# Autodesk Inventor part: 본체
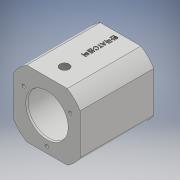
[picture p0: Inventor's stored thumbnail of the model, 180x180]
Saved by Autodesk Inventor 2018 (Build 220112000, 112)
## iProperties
Created: 2020-02
Part Number: 본체
Material: 일반
Document SubType Name: Modeling
Designer: USER
Density: 1 g/cm^3
Appearance: 기본값
Author: USER
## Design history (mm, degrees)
sketch "스케치1"
  geometry: L1 (32, -32)-(-32, -32); L2 (-32, -32)-(-32, 32); L3 (-32, 32)-(32, 32); L4 (32, 32)-(32, -32); L5 (32, -32)-(-32, 32); L6 (-32, -32)-(32, 32); 1 further point
  constraints: 12 end point, 2 midpoint, 2 parallel, 1 horizontal, 1 perpendicular
  dimensions: "d0" = 64 distance of L2.end L3.end; "d1" = 64 distance of L1.end L2.end
extrude "돌출1" new body sketch "스케치1" distance "d2" = 71; taper "d3" = 0 deg
sketch "스케치2"
  geometry: C1 r 37.5 at (0, 0); 1 further point
  constraints: 1 centre point, 1 coincident
  dimensions: "d4" = 75 diameter of C1
extrude "돌출2" sketch "스케치2" distance "d5" = 71; taper "d6" = 0 deg
sketch "스케치4"
  geometry: C1 r 14 at (0, 0); 1 further point
  constraints: 1 centre point, 1 coincident
  dimensions: "d7" = 28 diameter of C1
extrude "돌출3" join sketch "스케치4" distance "d8" = 12; taper "d9" = 0 deg
sketch "스케치5"
  geometry: C1 r 20 at (0, 0); 1 further point
  constraints: 1 centre point, 1 coincident
  dimensions: "d10" = 40 diameter of C1
extrude "돌출4" cut sketch "스케치5" distance "d11" = 62; taper "d12" = 0 deg
sketch "스케치6"
  geometry: 2 further points
  constraints: 1 coincident
hole "구멍1" sketch "스케치6" at (0, 0) diameter "d13" = 8.917; stored, may be unused: countersink angle "d17" = 90 deg, drill point angle "d19" = 118 deg; dims "d14" = 14, "d15" = 4, "d16" = 2, "d18" = 17
sketch "스케치7"
  geometry: C1 r 2 at (0, 0); 1 further point
  constraints: 1 centre point, 1 coincident
  dimensions: "d20" = 4 diameter of C1
extrude "돌출5" cut sketch "스케치7" distance "d21" = 62; taper "d22" = 0 deg
sketch "스케치8"
  geometry: L1 (0, 0)-(-22.517, 13); L2 (0, 0)-(0, 32); L3 (-19.551, 32)-(19.551, 32) reference; L4 (0, 0)-(22.517, 13); C1 r 2 at (0, 0) reference; A1 r 26 centre (0, 0) between (-22.517, 13) and (0, -26); 2 further points
  constraints: 6 end point, 2 coincident, 2 point on circle, 1 centre point, 1 midpoint, 1 symmetric about line
  dimensions: "d23" = 52 diameter of A1; "d24" = 60 deg angle of L2 L1
hole "구멍2" sketch "스케치8" at (-22.517, 13), (22.517, 13), (0, -26) diameter "d25" = 3.242; stored, may be unused: countersink angle "d29" = 90 deg, drill point angle "d31" = 118 deg; dims "d26" = 10, "d27" = 4, "d28" = 2, "d30" = 12
sketch "스케치9"
  geometry: A1 r 26 centre (0, 0) between (0, -26) and (-26, 0); 3 further points
  constraints: 4 point on circle, 1 centre point, 1 coincident
  dimensions: "d32" = 52 diameter of A1
hole "구멍3" sketch "스케치9" at (0, -26), (-26, 0), (0, 26), (26, 0) diameter "d33" = 3.242; stored, may be unused: countersink angle "d37" = 90 deg, drill point angle "d39" = 118 deg; dims "d34" = 10, "d35" = 4, "d36" = 2, "d38" = 12
sketch "스케치10"
  geometry: L1 (39.102, 71)-(51.551, 71) reference; L2 (39.102, 0)-(0, 0) reference; 3 further points
  constraints: 1 midpoint, 1 vertical alignment, 1 other
  dimensions: "d40" = 20 distance from line of L1 point (19.551, 51)
feature "엠보싱1" sketch "스케치10" dims "d0" = 64, "d1" = 64, "d41" = 0.5, "d42" = 0
sketch "스케치11"
  geometry: L1 (39.102, 0)-(0, 0) reference; 3 further points
  constraints: 1 midpoint, 1 vertical alignment
  dimensions: "d43" = 17 distance of point (19.551, 0) point (19.551, 17)
hole "구멍4" sketch "스케치11" at (19.551, 17) diameter "d44" = 8.917; stored, may be unused: countersink angle "d48" = 90 deg, drill point angle "d50" = 118 deg; dims "d45" = 6, "d46" = 4, "d47" = 2, "d49" = 9
sketch "스케치12"
  geometry: C1 r 4.458 at (19.551, 17) reference; C2 r 2 at (19.551, 17); 1 further point
  constraints: 1 centre point, 1 coincident
  dimensions: "d51" = 4 diameter of C2
extrude "돌출6" cut sketch "스케치12" distance "d52" = 20; taper "d53" = 0 deg
chamfer "모따기2" distance "d57" = 1.8; stored, may be unused: second distance "d58" = 2, angle "d59" = 15 deg
chamfer "모따기3" distance "d60" = 1; stored, may be unused: second distance "d61" = 2, angle "d62" = 15 deg
node "솔리드1"
